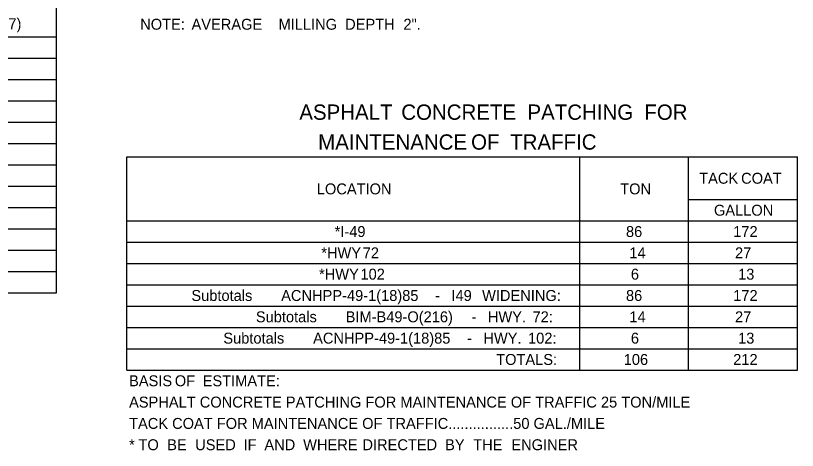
# Model space of a CAD drawing. Extents: x 1226561 to 1228164, y 151309 to 152305.
# Drawn here: x 1227627.4 to 1227985, y 151344.2 to 151543 of the extents above; entities that cross this region are included whole.
import ezdxf

# ---------------------------------------------------------------- set-up
doc = ezdxf.new("R2010")
doc.units = 0
doc.layers.add('R_Dimension', color=7, linetype='Continuous')

msp = doc.modelspace()

# ---------------------------------------------------------------- linework, layer by layer
at = {"layer": 'R_Dimension'}
for p, q in [((1227646.11, 151416.28), (1227646.11, 151552.78)), ((1227407.73, 151533.28), (1227646.11, 151533.28)), ((1227218.58, 151523.53), (1227646.11, 151523.53)), ((1227218.58, 151513.78), (1227646.11, 151513.78)), ((1227218.58, 151504.03), (1227646.11, 151504.03)), ((1227218.58, 151494.28), (1227646.11, 151494.28)), ((1227218.58, 151484.53), (1227646.11, 151484.53)), ((1227678.32, 151478.36), (1227984.95, 151478.36)), ((1227678.32, 151380.86), (1227678.32, 151478.36)), ((1227885.5, 151380.86), (1227885.5, 151478.36)), ((1227935.23, 151380.86), (1227935.23, 151478.36)), ((1227984.95, 151380.86), (1227984.95, 151478.36)), ((1227218.58, 151474.78), (1227646.11, 151474.78)), ((1227218.58, 151465.03), (1227646.11, 151465.03)), ((1227935.23, 151458.86), (1227984.95, 151458.86)), ((1227218.58, 151455.28), (1227646.11, 151455.28)), ((1227678.32, 151449.11), (1227984.95, 151449.11)), ((1227218.58, 151445.53), (1227646.11, 151445.53)), ((1227678.32, 151439.36), (1227984.95, 151439.36)), ((1227218.58, 151435.78), (1227646.11, 151435.78)), ((1227678.32, 151429.61), (1227984.95, 151429.61)), ((1227218.58, 151426.03), (1227646.11, 151426.03)), ((1227678.32, 151419.86), (1227984.95, 151419.86)), ((1227218.58, 151416.28), (1227646.11, 151416.28)), ((1227678.32, 151410.11), (1227984.95, 151410.11)), ((1227678.32, 151400.36), (1227984.95, 151400.36)), ((1227678.32, 151390.61), (1227984.95, 151390.61)), ((1227678.32, 151380.86), (1227984.95, 151380.86))]:
    msp.add_line(p, q, dxfattribs=at)

# ---------------------------------------------------------------- texts
for s, height, p in [(' 7)', 5, (1227622.24, 151536.78)), ('NOTE:', 5, (1227684.37, 151536.54)), ('  AVERAGE', 5, (1227704.14, 151536.54)), (' MILLING', 5, (1227745.79, 151536.54)), (' DEPTH', 5, (1227776.26, 151536.54)), (' 2".', 5, (1227802.91, 151536.54)), ('ASPHALT', 7, (1227757.15, 151495.34)), (' CONCRETE', 7, (1227801.19, 151495.34)), (' PATCHING', 7, (1227858.9, 151495.34)), (' FOR', 7, (1227912.36, 151495.34)), ('MAINTENANCE', 7, (1227765.77, 151481.69)), (' OF', 7, (1227833.12, 151481.69)), (' TRAFFIC', 7, (1227850.98, 151481.69)), ('TACK', 5, (1227940.05, 151466.11)), (' COAT', 5, (1227957.37, 151466.11)), ('LOCATION', 5, (1227765.16, 151461.24)), ('TON', 5, (1227903.93, 151461.24)), ('GALLON', 5, (1227946.8, 151451.49)), ('*I-49', 5, (1227773.31, 151441.74)), ('86', 5, (1227906.57, 151441.74)), ('172', 5, (1227955.6, 151441.74)), ('*HWY', 5, (1227767.21, 151431.99)), (' 72', 5, (1227784.29, 151431.99)), ('14', 5, (1227908.12, 151431.99)), ('27', 5, (1227956.43, 151431.99)), ('*HWY', 5, (1227766.18, 151422.24)), (' 102', 5, (1227783.27, 151422.24)), ('6', 5, (1227908.81, 151422.24)), ('13', 5, (1227957.85, 151422.24)), ('Subtotals', 5, (1227707.79, 151412.49)), (' ACNHPP-49-1(18)85', 5, (1227747, 151412.49)), (' -', 5, (1227817.44, 151412.49)), (' I49', 5, (1227824.88, 151412.49)), (' WIDENING:', 5, (1227838.89, 151412.49)), ('86', 5, (1227906.57, 151412.49)), ('172', 5, (1227955.6, 151412.49)), ('Subtotals', 5, (1227737.28, 151402.74)), (' BIM-B49-O(216)', 5, (1227776.49, 151402.74)), (' HWY.', 5, (1227841.53, 151402.74)), (' 72:', 5, (1227861.96, 151402.74)), ('14', 5, (1227908.12, 151402.74)), ('27', 5, (1227956.43, 151402.74)), (' -', 5, (1227834.09, 151402.74)), ('Subtotals', 5, (1227722.4, 151392.99)), (' ACNHPP-49-1(18)85', 5, (1227761.61, 151392.99)), (' HWY.', 5, (1227839.48, 151392.99)), (' 102:', 5, (1227859.92, 151392.99)), ('6', 5, (1227908.81, 151392.99)), ('13', 5, (1227957.85, 151392.99)), (' -', 5, (1227832.04, 151392.99)), ('TOTALS:', 5, (1227847.2, 151383.24)), ('106', 5, (1227905.54, 151383.24)), ('212', 5, (1227955.6, 151383.24)), ('BASIS', 5, (1227679.29, 151373.49)), (' OF', 5, (1227698.35, 151373.49)), (' ESTIMATE:', 5, (1227711.1, 151373.49)), ('ASPHALT CONCRETE PATCHING FOR MAINTENANCE OF TRAFFIC 25 TON/MILE', 5, (1227679.29, 151363.74)), ('TACK COAT FOR MAINTENANCE OF TRAFFIC................50 GAL./MILE', 5, (1227679.29, 151353.99)), ('*', 5, (1227679.29, 151344.24)), (' TO', 5, (1227681.73, 151344.24)), (' BE', 5, (1227694.88, 151344.24)), (' USED', 5, (1227707.68, 151344.24)), (' IF', 5, (1227729.8, 151344.24)), (' AND', 5, (1227739.33, 151344.24)), (' WHERE', 5, (1227757.05, 151344.24)), (' DIRECTED', 5, (1227784.17, 151344.24)), (' BY', 5, (1227821.97, 151344.24)), (' THE', 5, (1227834.84, 151344.24)), (' ENGINER', 5, (1227852.28, 151344.24))]:
    msp.add_text(s, height=height, dxfattribs=at).set_placement(p)

doc.saveas('drawing.dxf')
